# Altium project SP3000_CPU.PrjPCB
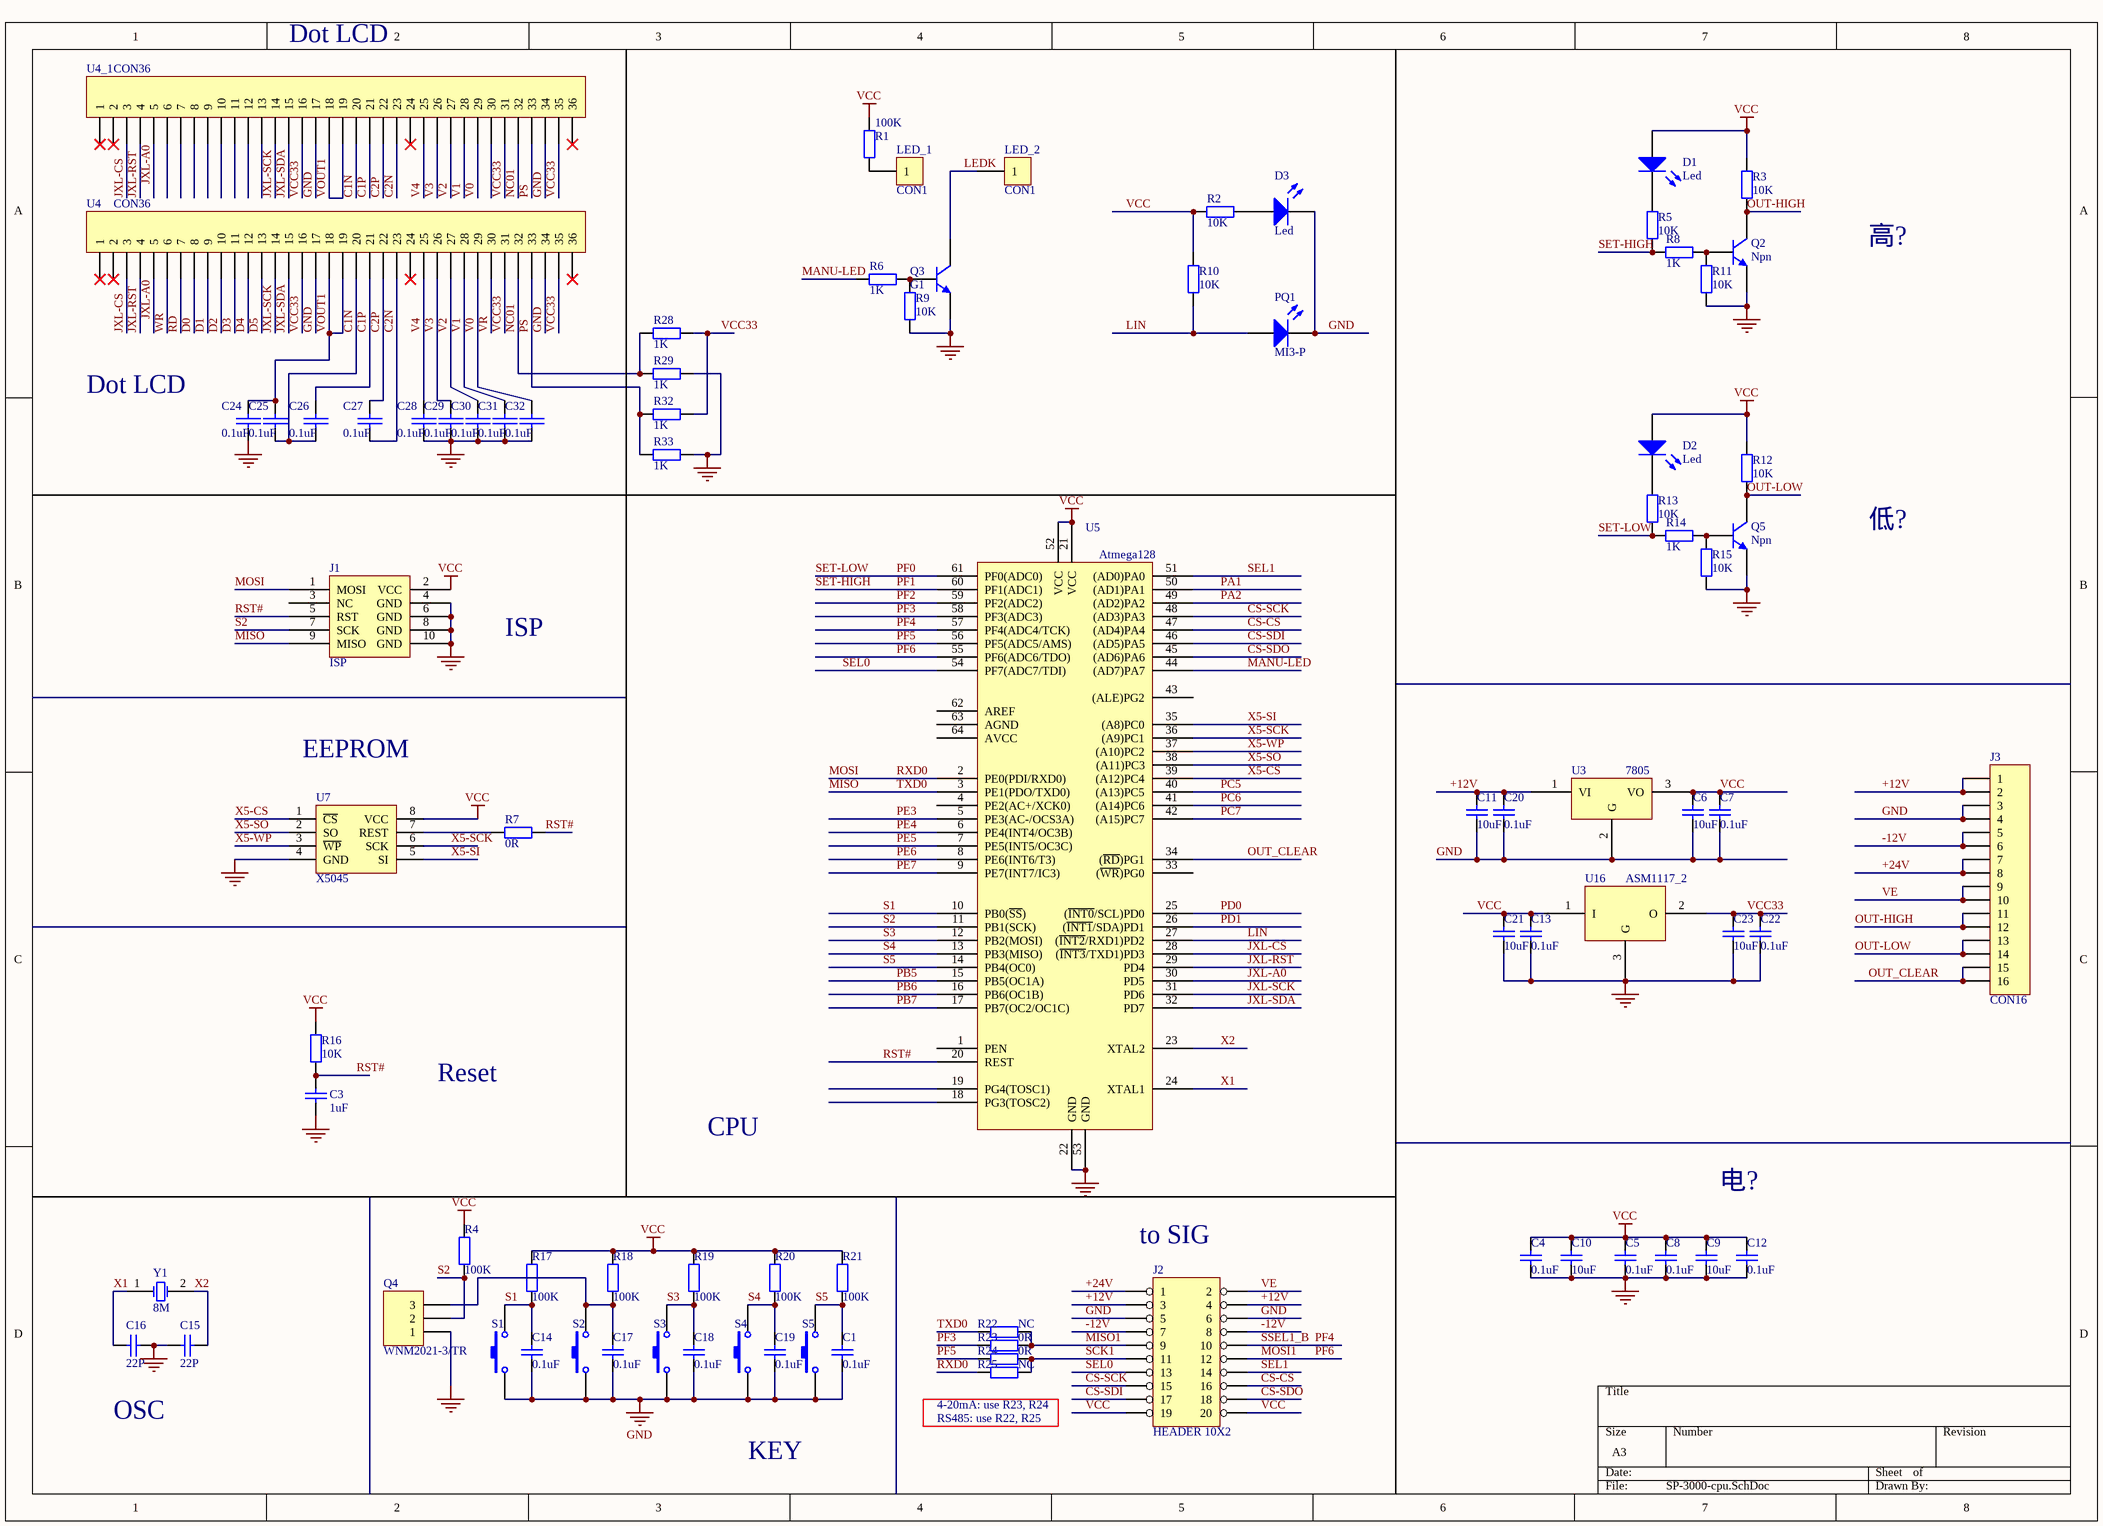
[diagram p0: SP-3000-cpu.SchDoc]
1 sheet, 85 parts. Net scope: global (net labels, ports and power ports of the same name join across sheets).
Board file: SP3000_CPU_V5.2.PcbDoc

## Sheet SP-3000-cpu.SchDoc
size A3; SheetNumber: 0; SheetTotal: 0

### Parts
C1  0.1uF  [0603]
C3  1uF  [0603]
C4  0.1uF  [0603]
C5  0.1uF  [0603]
C6  10uF  [B]
C7  0.1uF  [0603]
C8  0.1uF  [0603]
C9  10uF  [0603]
C10  10uF  [B]
C11  10uF  [B]
C12  0.1uF  [0603]
C13  0.1uF  [0603]
C14  0.1uF  [0603]
C15  22P  [0603]
C16  22P  [0603]
C17  0.1uF  [0603]
C18  0.1uF  [0603]
C19  0.1uF  [0603]
C20  0.1uF  [0603]
C21  10uF  [B]
C22  0.1uF  [0603]
C23  10uF  [B]
C24  0.1uF  [0603]
C25  0.1uF  [0603]
C26  0.1uF  [0603]
C27  0.1uF  [0603]
C28  0.1uF  [0603]
C29  0.1uF  [0603]
C30  0.1uF  [0603]
C31  0.1uF  [0603]
C32  0.1uF  [0603]
D1  Led  [LED]
D2  Led  [LED]
D3  Led  [LED]
J1  ISP  [IDC10]
J2  HEADER 10X2  [IDC20]
J3  CON16  [IDC16]
LED_1  CON1  [LEC_A]
LED_2  CON1  [LEC_A]
PQ1  MI3-P  [LED]
Q2  Npn  [9013]
Q3  G1  [9013]
Q4  WNM2021-3/TR  [9013]
Q5  Npn  [9013]
R1  100K  [0603]
R2  10K  [0603]
R3  10K  [0603]
R4  100K  [0603]
R5  10K  [0603]
R6  1K  [0603]
R7  0R  [0603]
R8  1K  [0603]
R9  10K  [0603]
R10  10K  [0603]
R11  10K  [0603]
R12  10K  [0603]
R13  10K  [0603]
R14  1K  [0603]
R15  10K  [0603]
R16  10K  [0603]
R17  100K  [0603]
R18  100K  [0603]
R19  100K  [0603]
R20  100K  [0603]
R21  100K  [0603]
R22  NC  [0603]
R23  0R  [0603]
R24  0R  [0603]
R25  NC  [0603]
R28  1K  [0603]
R29  1K  [0603]
R32  1K  [0603]
R33  1K  [0603]
S1  (no value)  [SW3-DIP]
S2  (no value)  [SW3-DIP]
S3  (no value)  [SW3-DIP]
S4  (no value)  [SW3-DIP]
S5  (no value)  [SW3-DIP]
U3  7805  [7805]
U4  CON36  [LCD_36]
U4_1  CON36  [LCD36-JLX]
U5  Atmega128  [Quad64]
U7  X5045  [SOP8]
U16  ASM1117_2  [MP04A_N]
Y1  8M  [CY]

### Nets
GND: C1.1 C3.2 C4.1 C5.1 C6.2 C7.1 C8.1 C9.1 C10.2 C11.2 C12.1 C13.1 C14.1 C15.1 C16.2 C17.1 C18.1 C19.1 C20.2 C21.2 C22.2 C23.2 C24.2 C28.2 C29.2 C30.2 C31.2 C32.2 D3.2(K) J1.4(GND) J1.6(GND) J1.8(GND) J1.10(GND) J2.5 J2.6 J3.3 J3.4 PQ1.2(K) Q2.2(E) Q3.2(E) Q4.1 Q5.2(E) R9.1 R11.1 R15.1 R29.1 R33.1 S1.1 S2.1 S3.1 S4.1 S5.1 U3.2(G) U4.17 U4.34 U4_1.17 U4_1.34 U5.22(GND) U5.53(GND) U7.4(GND) U16.3(G)
VCC: C4.2 C5.2 C6.1 C7.2 C8.2 C9.2 C10.1 C12.2 C13.2 C21.1 D1.1(A) D2.1(A) J1.2(VCC) J2.19 J2.20 R1.1 R2.1 R3.2 R4.2 R10.2 R12.2 R16.2 R17.2 R18.2 R19.2 R20.2 R21.2 U3.3(VO) U5.21(VCC) U5.52(VCC) U7.8(VCC) U16.1(I)
+12V: C11.1 C20.1 J2.3 J2.4 J3.1 J3.2 U3.1(VI)
+24V: J2.1 J3.7 J3.8
-12V: J2.7 J2.8 J3.5 J3.6
C1N: C25.2 C26.2 U4.20 U4_1.20
C1P: C26.1 U4.21 U4_1.21
C2N: C27.2 U4.23 U4_1.23
C2P: C27.1 U4.22 U4_1.22
CS-CS: J2.16 U5.47((AD4)PA4)
CS-SCK: J2.15 U5.48((AD3)PA3)
CS-SDI: J2.17 U5.46((AD5)PA5)
CS-SDO: J2.18 U5.45((AD6)PA6)
D0: U4.8
D1: U4.9
D2: U4.10
D3: U4.11
D4: U4.12
D5: U4.13
JXL-A0: U4.5 U4_1.5 U5.30(PD5)
JXL-CS: U4.3 U4_1.3 U5.28((~{INT3}/TXD1)PD3)
JXL-RST: U4.4 U4_1.4 U5.29(PD4)
JXL-SCK: U4.14 U4_1.14 U5.31(PD6)
JXL-SDA: U4.15 U4_1.15 U5.32(PD7)
LEDK: LED_2.1 Q3.3(C)
LIN: PQ1.1(A) R10.1 U5.27((~{INT2}/RXD1)PD2)
MANU-LED: R6.2 U5.44((AD7)PA7)
MISO: J1.9(MISO) R22.2 U5.3(PE1(PDO/TXD0))  [also labelled TXD0]
MISO1: J2.9 R22.1 R23.1
MOSI: J1.1(MOSI) R25.2 U5.2(PE0(PDI/RXD0))  [also labelled RXD0]
MOSI1: J2.12 U5.55(PF6(ADC6/TDO))  [also labelled PF6]
NC01: R28.2 R29.2 U4.32 U4_1.32
OUT-HIGH: J3.11 J3.12 Q2.3(C) R3.1
OUT-LOW: J3.13 J3.14 Q5.3(C) R12.1
OUT_CLEAR: J3.15 J3.16 U5.34((~{RD})PG1)
PA1: U5.50((AD1)PA1)
PA2: U5.49((AD2)PA2)
PB5: U5.15(PB5(OC1A))
PB6: U5.16(PB6(OC1B))
PB7: U5.17(PB7(OC2/OC1C))
PC5: U5.40((A13)PC5)
PC6: U5.41((A14)PC6)
PC7: U5.42((A15)PC7)
PD0: U5.25((~{INT0}/SCL)PD0)
PD1: U5.26((~{INT1}/SDA)PD1)
PE3: U5.5(PE3(AC-/OCS3A))
PE4: U5.6(PE4(INT4/OC3B))
PE5: U5.7(PE5(INT5/OC3C))
PE6: U5.8(PE6(INT6/T3))
PE7: U5.9(PE7(INT7/IC3))
PF0: R13.1 R14.1 U5.61(PF0(ADC0))  [also labelled SET-LOW]
PF1: R5.1 R8.1 U5.60(PF1(ADC1))  [also labelled SET-HIGH]
PF2: U5.59(PF2(ADC2))
PF3: R23.2 U5.58(PF3(ADC3))
PF4: J2.10 U5.57(PF4(ADC4/TCK))  [also labelled SSEL1_B]
PF5: R24.2 U5.56(PF5(ADC5/AMS))
PS: R32.2 R33.2 U4.33 U4_1.33
RD: U4.7
RST#: C3.1 J1.5(RST) R7.1 R16.1 U5.20(REST)
S1: C14.2 R17.1 S1.2 U5.10(PB0(~{SS}))
S2: J1.7(SCK) Q4.2 R4.1 U5.11(PB1(SCK))
S3: C18.2 R19.1 S3.2 U5.12(PB2(MOSI))
S4: C19.2 R20.1 S4.2 U5.13(PB3(MISO))
S5: C1.2 R21.1 S5.2 U5.14(PB4(OC0))
SCK1: J2.11 R24.1 R25.1
SEL0: J2.13 U5.54(PF7(ADC7/TDI))
SEL1: J2.14 U5.51((AD0)PA0)
V0: C32.1 U4.29 U4_1.29
V1: C31.1 U4.28 U4_1.28
V2: C30.1 U4.27 U4_1.27
V3: C29.1 U4.26 U4_1.26
V4: C28.1 U4.25 U4_1.25
VCC33: C22.1 C23.1 R28.1 R32.1 U4.16 U4.31 U4.35 U4_1.16 U4_1.31 U4_1.35 U16.2(O)
VE: J2.2 J3.9 J3.10
VOUT1: C24.1 C25.1 U4.18 U4.19 U4_1.18 U4_1.19
VR: U4.30
WR: U4.6
X1: C16.1 U5.24(XTAL1) Y1.1(OSC1)
X2: C15.2 U5.23(XTAL2) Y1.2(OSC2)
X5-CS: U5.39((A12)PC4) U7.1(~{CS})
X5-SCK: U5.36((A9)PC1) U7.6(SCK)
X5-SI: U5.35((A8)PC0) U7.5(SI)
X5-SO: U5.38((A11)PC3) U7.2(SO)
X5-WP: U5.37((A10)PC2) U7.3(~{WP})
NetC17_2: C17.2 Q4.3 R18.1 S2.2
NetD1_2: D1.2(K) R5.2
NetD2_2: D2.2(K) R13.2
NetD3_1: D3.1(A) R2.2
NetLED_1_1: LED_1.1 R1.2
NetQ2_1: Q2.1(B) R8.2 R11.2
NetQ3_1: Q3.1(B) R6.1 R9.2
NetQ5_1: Q5.1(B) R14.2 R15.2
NetR7_2: R7.2 U7.7(REST)

Not connected (* = marked no-connect by the designer): J1 3(NC); U4 1* 2* 24* 36*; U4_1 1* 2* 6 7 8 9 10 11 12 13 24* 30 36*; U5 1(PEN) 4(PE2(AC+/XCK0)) 18(PG3(TOSC2)) 19(PG4(TOSC1)) 33((~{WR})PG0) 43((ALE)PG2) 62(AREF) 63(AGND) 64(AVCC)

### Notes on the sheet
- Dot LCD
- 高?
- 低?
- ISP
- EEPROM
- Reset
- CPU
- 电?
- (near J2) to SIG
- 4-20mA: use R23, R24
- OSC
- KEY
- RS485: use R22, R25

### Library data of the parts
C1 C3-C23 = Cap: C?
C24-C32 = CAP: Capacitor
D1-D3 PQ1 = Led: D?
J1 = isp: U?
J3 = CON16: Connector
LED_1 LED_2 = CON1: Connector
Q2 Q3 Q5 = Npn: Q?
Q4 = Header 3: N-Channel, 20V, 0.89A, Small Signal MOSFET
R1-R25 R28 R29 R32 R33 = Res: R?
S1-S5 = Sw-pb: S?
U3 = 7805: U
U4 U4_1 = CON36: Connector
U5 = Atmega128: U?
Y1 = Xtal: Y?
